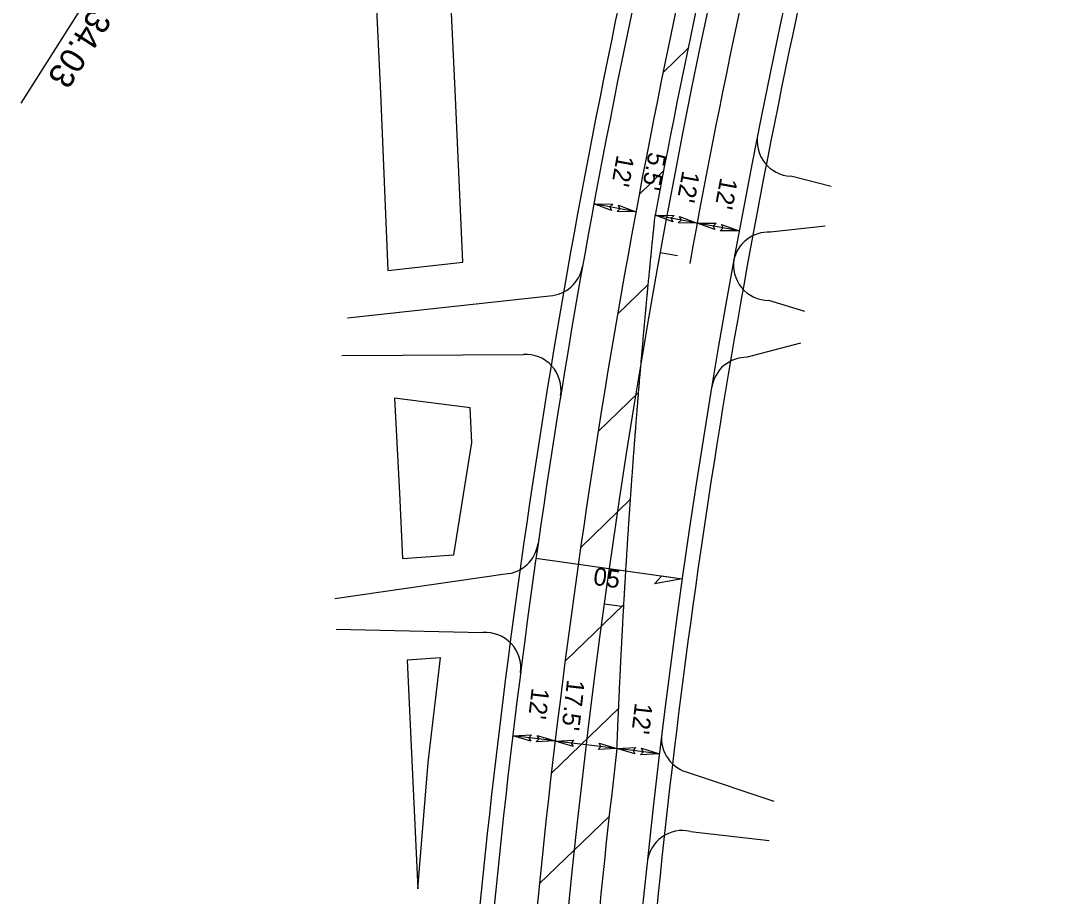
# Model space of a CAD drawing. Extents: x 1778969 to 1790720, y 807089 to 817794.
# Drawn here: x 1780836.5 to 1781129.1, y 811760.3 to 812006.4 of the extents above; entities that cross this region are included whole.
import ezdxf

# ---------------------------------------------------------------- set-up
doc = ezdxf.new("R2010")
doc.units = 0
for name, color, linetype in [('Prop Dimension', 7, 'Continuous'), ('Prop Dimension Text', 7, 'Continuous'), ('Prop EOT', 7, 'Continuous'), ('Prop Hatching', 7, 'Continuous'), ('Prop Horizontal Alignment', 7, 'Continuous'), ('Prop Horizontal Alignment Station Label', 7, 'Continuous'), ('Prop Horizontal Alignment Tick Small', 7, 'Continuous'), ('Prop Lane Lines', 7, 'Continuous'), ('Prop Paved Shoulder', 7, 'Continuous'), ('Prop Rem of Exist Asph Pvmt', 7, 'Continuous'), ('Prop Superelevation  Arrow CELL', 7, 'Continuous'), ('Prop Superelevation Label', 7, 'Continuous'), ('Prop Terminator CELL', 7, 'Continuous')]:
    doc.layers.add(name, color=color, linetype=linetype)

msp = doc.modelspace()

# ---------------------------------------------------------------- linework, layer by layer
at = {"layer": 'Prop Dimension'}
for p, q in [((1781009.33, 811952.75), (1780997.53, 811954.94)), ((1781026.53, 811949.55), (1781014.73, 811951.74)), ((1781038.33, 811947.36), (1781026.53, 811949.55)), ((1780986.64, 811803.98), (1780974.73, 811805.43)), ((1781004.01, 811801.85), (1780986.63, 811803.89)), ((1781015.92, 811800.39), (1781004.01, 811801.85))]:
    msp.add_line(p, q, dxfattribs=at)
at = {"layer": 'Prop EOT'}
for p, q in [((1781064.2, 811959.83), (1781052.81, 811962.71)), ((1781062.46, 811948.72), (1781047.16, 811947)), ((1780928.34, 811922.95), (1780985.09, 811929.11)), ((1781056.75, 811924.68), (1781046.64, 811927.78)), ((1781055.55, 811915.8), (1781040.58, 811911.84)), ((1780926.74, 811912.29), (1780977.7, 811912.64)), ((1780924.7, 811843.99), (1780972.6, 811850.91)), ((1780925.1, 811835.4), (1780966.34, 811834.45)), ((1781024.32, 811795.02), (1781048.12, 811787.08)), ((1781024.62, 811778.55), (1781046.81, 811775.95))]:
    msp.add_line(p, q, dxfattribs=at)
for centre, radius, start, end in [((1783308.81, 811525.98), 2309.25, 153.74801, 174.52695), ((1783308.81, 811525.98), 2350.75, 165.94828, 174.52695), ((1781053.37, 811972.7), 10, 168.7968, 266.788), ((1781046.6, 811937.02), 10, 86.788, 169.7017), ((1781046.74, 811937.78), 10, 169.6825, 269.4518), ((1780984.49, 811939.1), 10, 273.4494, 349.9216), ((1780978.3, 811902.66), 10, 350.8187, 93.4494), ((1781040.49, 811901.84), 10, 89.4518, 170.5916), ((1780971.94, 811860.89), 10, 273.8323, 351.8442), ((1780967.01, 811824.48), 10, 352.7359, 93.8323), ((1781026.52, 811804.77), 10, 173.0355, 257.2923), ((1781022.42, 811768.8), 10, 77.2923, 173.9378)]:
    msp.add_arc(centre, radius, start, end, dxfattribs=at)
at = {"layer": 'Prop Hatching'}
for p, q in [((1781023.93, 811998.63), (1781016.94, 811991.88)), ((1781017.09, 811964.24), (1781010.24, 811957.63)), ((1781012.79, 811932.3), (1781004.18, 811923.99)), ((1781010.08, 811901.9), (1780998.71, 811890.92)), ((1781007.81, 811871.91), (1780993.81, 811858.4)), ((1781005.95, 811842.33), (1780989.43, 811826.4)), ((1781004.48, 811813.12), (1780985.57, 811794.88)), ((1781001.81, 811782.75), (1780982.19, 811763.82))]:
    msp.add_line(p, q, dxfattribs=at)
at = {"layer": 'Prop Horizontal Alignment'}
msp.add_arc((1783308.81, 811525.98), 2330, 144.08998, 185.35942, dxfattribs=at)
at = {"layer": 'Prop Horizontal Alignment Station Label'}
msp.add_line((1780895.08, 812075.57), (1780836.52, 811983.29), dxfattribs=at)
at = {"layer": 'Prop Horizontal Alignment Tick Small'}
for p, q in [((1781016.13, 811941.31), (1781021.05, 811940.42)), ((1781000.42, 811842.56), (1781005.37, 811841.88))]:
    msp.add_line(p, q, dxfattribs=at)
at = {"layer": 'Prop Lane Lines'}
for radius, start, end in [(2338.75, 165.86471, 174.52217), (2333.25, 165.86487, 169.48591), (2321.25, 165.86487, 169.77028), (2321.25, 173.17447, 174.52695)]:
    msp.add_arc((1783308.81, 811525.98), radius, start, end, dxfattribs=at)
for points in [[(1781010.07, 811901.77), (1781010.13, 811902.45), (1781010.19, 811903.13), (1781010.24, 811903.8), (1781010.3, 811904.48), (1781010.35, 811905.15), (1781010.41, 811905.83), (1781010.47, 811906.5), (1781010.53, 811907.18), (1781010.58, 811907.85), (1781010.64, 811908.53), (1781010.7, 811909.2), (1781010.76, 811909.88), (1781010.81, 811910.55), (1781010.87, 811911.23), (1781010.93, 811911.9), (1781010.99, 811912.58), (1781011.05, 811913.25), (1781011.11, 811913.93), (1781011.17, 811914.61), (1781011.23, 811915.28), (1781011.29, 811915.96), (1781011.35, 811916.63), (1781011.41, 811917.31), (1781011.47, 811917.98), (1781011.53, 811918.66), (1781011.59, 811919.33), (1781011.65, 811920.01), (1781011.71, 811920.68), (1781011.77, 811921.36), (1781011.83, 811922.03), (1781011.89, 811922.71), (1781011.96, 811923.38), (1781012.02, 811924.06), (1781012.08, 811924.73), (1781012.14, 811925.41), (1781012.21, 811926.09), (1781012.27, 811926.76), (1781012.33, 811927.44), (1781012.39, 811928.11), (1781012.46, 811928.79), (1781012.52, 811929.46), (1781012.59, 811930.14), (1781012.65, 811930.81), (1781012.71, 811931.49), (1781012.78, 811932.16), (1781012.84, 811932.84), (1781012.91, 811933.51), (1781012.97, 811934.19), (1781013.04, 811934.86), (1781013.1, 811935.54), (1781013.17, 811936.21), (1781013.24, 811936.89), (1781013.3, 811937.56), (1781013.37, 811938.24), (1781013.43, 811938.91), (1781013.5, 811939.59), (1781013.57, 811940.27), (1781013.63, 811940.94), (1781013.7, 811941.62), (1781013.77, 811942.29), (1781013.84, 811942.97), (1781013.9, 811943.64), (1781013.97, 811944.32), (1781014.04, 811944.99), (1781014.11, 811945.67), (1781014.18, 811946.34), (1781014.25, 811947.02), (1781014.32, 811947.69), (1781014.39, 811948.37), (1781014.45, 811949.04), (1781014.52, 811949.72), (1781014.59, 811950.39), (1781014.66, 811951.07), (1781014.73, 811951.74)], [(1781006.5, 811851.8), (1781006.54, 811852.48), (1781006.58, 811853.15), (1781006.62, 811853.83), (1781006.67, 811854.5), (1781006.71, 811855.18), (1781006.75, 811855.85), (1781006.79, 811856.53), (1781006.83, 811857.2), (1781006.88, 811857.88), (1781006.92, 811858.55), (1781006.96, 811859.23), (1781007.01, 811859.91), (1781007.05, 811860.58), (1781007.09, 811861.26), (1781007.14, 811861.93), (1781007.18, 811862.61), (1781007.23, 811863.28), (1781007.27, 811863.96), (1781007.31, 811864.63), (1781007.36, 811865.31), (1781007.4, 811865.98), (1781007.45, 811866.66), (1781007.49, 811867.33), (1781007.54, 811868.01), (1781007.59, 811868.68), (1781007.63, 811869.36), (1781007.68, 811870.03), (1781007.72, 811870.71), (1781007.77, 811871.38), (1781007.82, 811872.06), (1781007.87, 811872.74), (1781007.91, 811873.41), (1781007.96, 811874.09), (1781008.01, 811874.76), (1781008.06, 811875.44), (1781008.1, 811876.11), (1781008.15, 811876.79), (1781008.2, 811877.46), (1781008.25, 811878.14), (1781008.3, 811878.81), (1781008.35, 811879.49), (1781008.4, 811880.16), (1781008.44, 811880.84), (1781008.49, 811881.51), (1781008.54, 811882.19), (1781008.59, 811882.87), (1781008.64, 811883.54), (1781008.69, 811884.22), (1781008.75, 811884.89), (1781008.8, 811885.57), (1781008.85, 811886.24), (1781008.9, 811886.92), (1781008.95, 811887.59), (1781009, 811888.27), (1781009.05, 811888.94), (1781009.1, 811889.62), (1781009.16, 811890.29), (1781009.21, 811890.97), (1781009.26, 811891.64), (1781009.31, 811892.32), (1781009.37, 811893), (1781009.42, 811893.67), (1781009.47, 811894.35), (1781009.53, 811895.02), (1781009.58, 811895.7), (1781009.64, 811896.37), (1781009.69, 811897.05), (1781009.74, 811897.72), (1781009.8, 811898.4), (1781009.85, 811899.07), (1781009.91, 811899.75), (1781009.96, 811900.42), (1781010.02, 811901.1), (1781010.07, 811901.77)], [(1781004.01, 811801.85), (1781004.06, 811803.2), (1781004.09, 811803.87), (1781004.12, 811804.55), (1781004.14, 811805.22), (1781004.17, 811805.9), (1781004.2, 811806.57), (1781004.23, 811807.25), (1781004.26, 811807.92), (1781004.28, 811808.6), (1781004.31, 811809.27), (1781004.34, 811809.95), (1781004.37, 811810.62), (1781004.4, 811811.3), (1781004.43, 811811.97), (1781004.46, 811812.65), (1781004.49, 811813.32), (1781004.52, 811814), (1781004.55, 811814.67), (1781004.58, 811815.35), (1781004.61, 811816.02), (1781004.64, 811816.7), (1781004.67, 811817.37), (1781004.7, 811818.05), (1781004.73, 811818.72), (1781004.76, 811819.4), (1781004.79, 811820.07), (1781004.83, 811820.75), (1781004.86, 811821.42), (1781004.89, 811822.1), (1781004.92, 811822.77), (1781004.95, 811823.45), (1781004.99, 811824.12), (1781005.02, 811824.8), (1781005.05, 811825.47), (1781005.09, 811826.15), (1781005.12, 811826.82), (1781005.15, 811827.5), (1781005.19, 811828.17), (1781005.22, 811828.85), (1781005.26, 811829.52), (1781005.29, 811830.2), (1781005.33, 811830.87), (1781005.36, 811831.55), (1781005.4, 811832.22), (1781005.43, 811832.9), (1781005.47, 811833.57), (1781005.5, 811834.25), (1781005.54, 811834.92), (1781005.57, 811835.6), (1781005.61, 811836.27), (1781005.65, 811836.95), (1781005.68, 811837.62), (1781005.72, 811838.3), (1781005.76, 811838.97), (1781005.79, 811839.65), (1781005.83, 811840.32), (1781005.87, 811841), (1781005.91, 811841.67), (1781005.95, 811842.35), (1781005.98, 811843.02), (1781006.02, 811843.7), (1781006.06, 811844.37), (1781006.1, 811845.05), (1781006.14, 811845.73), (1781006.18, 811846.4), (1781006.22, 811847.08), (1781006.26, 811847.75), (1781006.3, 811848.43), (1781006.34, 811849.1), (1781006.38, 811849.78), (1781006.42, 811850.45), (1781006.46, 811851.13), (1781006.5, 811851.8)]]:
    msp.add_spline(points, degree=3, dxfattribs=at)
at = {"layer": 'Prop Paved Shoulder'}
for radius, start in [(2354.75, 165.95604), (2305.25, 166.41947)]:
    msp.add_arc((1783308.81, 811525.98), radius, start, 174.52695, dxfattribs=at)
at = {"layer": 'Prop Rem of Exist Asph Pvmt'}
for p, q in [((1780939.66, 811936.25), (1780960.74, 811938.54)), ((1780962.75, 811897.65), (1780941.47, 811900.34)), ((1780958.13, 811856.25), (1780963.24, 811887.88)), ((1780943.73, 811855.29), (1780958.13, 811856.25)), ((1780954.4, 811827.32), (1780945.07, 811826.7)), ((1780950.95, 811797.94), (1780954.4, 811827.32)), ((1780948.04, 811762.44), (1780950.95, 811797.94))]:
    msp.add_line(p, q, dxfattribs=at)
for points in [[(1780960.74, 811938.54), (1780958.5, 811986.92), (1780955.97, 812042.2), (1780953.72, 812096.29), (1780953.05, 812110.3)], [(1780932.15, 812106.31), (1780932.57, 812095.06), (1780934.95, 812041.44), (1780937.57, 811986.07), (1780939.66, 811936.25)], [(1780941.47, 811900.34), (1780942.87, 811873.63), (1780943.73, 811855.29)], [(1780963.24, 811887.88), (1780963.24, 811887.88), (1780962.75, 811897.65)], [(1780945.07, 811826.7), (1780945.55, 811816.54), (1780948.04, 811762.44)]]:
    msp.add_lwpolyline(points, dxfattribs=at)
at = {"layer": 'Prop Superelevation  Arrow CELL'}
msp.add_line((1780981.25, 811855.38), (1781022.34, 811849.56), dxfattribs=at)
msp.add_lwpolyline([(1781022.34, 811849.56), (1781014.57, 811848.14), (1781016.62, 811850.37)], close=True, dxfattribs=at)
at = {"layer": 'Prop Terminator CELL'}
for points in [[(1781002.46, 811953.11), (1780997.53, 811954.94), (1781002.82, 811954.89), (1781002, 811954.11)], [(1781004.39, 811954.57), (1781009.33, 811952.75), (1781004.03, 811952.79), (1781004.85, 811953.58)], [(1781019.67, 811949.92), (1781014.73, 811951.74), (1781020.03, 811951.7), (1781019.21, 811950.91)], [(1781021.6, 811951.38), (1781026.53, 811949.55), (1781021.24, 811949.6), (1781022.06, 811950.38)], [(1781031.47, 811947.73), (1781026.53, 811949.55), (1781031.83, 811949.51), (1781031.01, 811948.72)], [(1781033.4, 811949.19), (1781038.33, 811947.36), (1781033.04, 811947.41), (1781033.86, 811948.19)], [(1780979.77, 811803.92), (1780974.73, 811805.43), (1780980.02, 811805.71), (1780979.25, 811804.88)], [(1780981.6, 811805.49), (1780986.64, 811803.98), (1780981.35, 811803.69), (1780982.12, 811804.53)], [(1780991.67, 811802.4), (1780986.63, 811803.89), (1780991.91, 811804.2), (1780991.15, 811803.36)], [(1780998.97, 811803.34), (1781004.01, 811801.85), (1780998.73, 811801.54), (1780999.49, 811802.38)], [(1781009.05, 811800.33), (1781004.01, 811801.85), (1781009.3, 811802.13), (1781008.53, 811801.3)], [(1781010.88, 811801.91), (1781015.92, 811800.39), (1781010.64, 811800.11), (1781011.41, 811800.94)]]:
    msp.add_lwpolyline(points, close=True, dxfattribs=at)

# ---------------------------------------------------------------- texts
at = {"layer": 'Prop Dimension Text'}
for s, rotation, p in [("12'", 259.4666, (1781004.01, 811968.91)), ("5.5'", 259.4666, (1781012.95, 811969.72)), ("12'", 259.4666, (1781022.42, 811964.44)), ("12'", 259.4666, (1781033.06, 811962.53)), ("17.5'", 263.6352, (1780990.01, 811821.38)), ("12'", 263.3468, (1780980.08, 811819.04)), ("12'", 263.3468, (1781009.08, 811814.84))]:
    msp.add_text(s, height=5, rotation=rotation, dxfattribs=at).set_placement(p)
at = {"layer": 'Prop Horizontal Alignment Station Label'}
msp.add_text('-Y2- PC Sta.  10+34.03', height=7, rotation=237.407, dxfattribs=at).set_placement((1780896.1, 812072.34))
at = {"layer": 'Prop Superelevation Label'}
msp.add_text('05', height=5, rotation=351.945, dxfattribs=at).set_placement((1780997.13, 811847.9))

doc.saveas('drawing.dxf')
